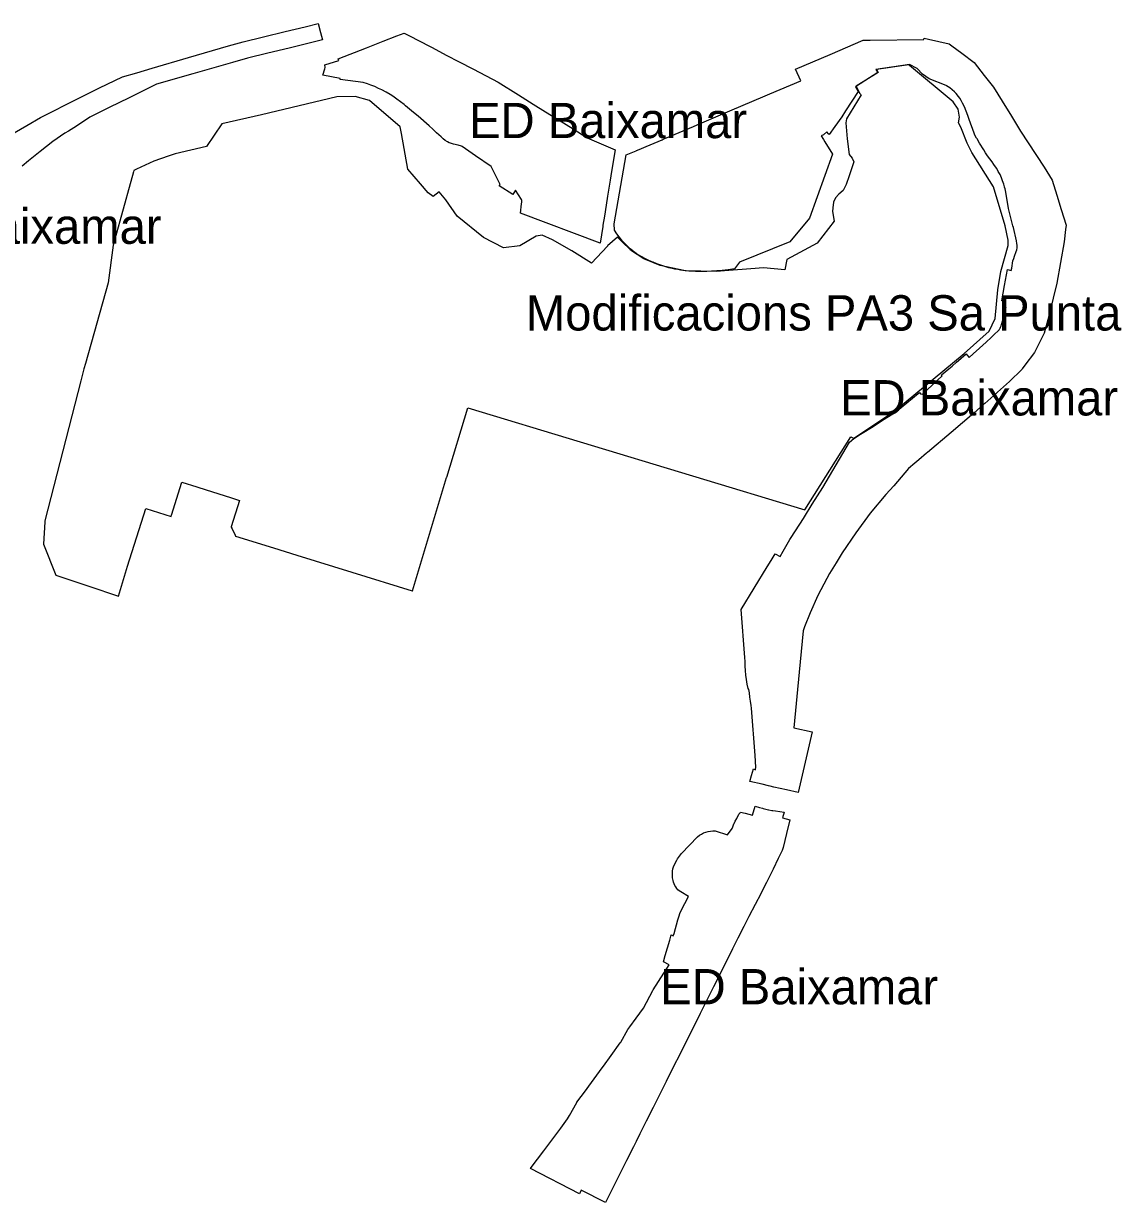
# Model space of a CAD drawing. Extents: x 599912 to 613490, y 4411003 to 4422920.
# Drawn here: x 608791.7 to 609165, y 4416011.2 to 4416412.1 of the extents above; entities that cross this region are included whole.
import ezdxf

# ---------------------------------------------------------------- set-up
doc = ezdxf.new("R2010")
doc.units = 0
doc.layers.add('Estudi de Detall', color=7, linetype='Continuous')
doc.layers.add('Sector amb disposicions transitòries', color=7, linetype='Continuous')

msp = doc.modelspace()

# ---------------------------------------------------------------- linework, layer by layer
at = {"layer": 'Estudi de Detall'}
msp.add_lwpolyline([(608788.56, 4416374.98), (608792.9, 4416377.42), (608797.5, 4416380.16), (608801.83, 4416382.34), (608806.24, 4416384.56), (608810.96, 4416386.95), (608817.59, 4416390.17), (608825.38, 4416393.95), (608830.19, 4416395.36), (608835.5, 4416396.92), (608847.81, 4416400.54), (608861.39, 4416404.46), (608866.43, 4416405.91), (608873.33, 4416407.58), (608880.64, 4416409.35), (608887.44, 4416410.99), (608891.88, 4416412.07), (608892.69, 4416409), (608893.36, 4416406.51), (608882.02, 4416403.74), (608874.78, 4416401.98), (608867.86, 4416400.29), (608862.79, 4416398.84), (608849.28, 4416395), (608836.96, 4416391.49), (608832.39, 4416389.23), (608827.66, 4416386.88), (608820.83, 4416383.49), (608814.23, 4416380.21), (608809.71, 4416377.21), (608806.96, 4416375.51), (608805.75, 4416374.76), (608801.64, 4416371.98), (608797.33, 4416368.59), (608793.4, 4416365.43), (608791.28, 4416363.64)], dxfattribs=at)
for points in [[(608907.15, 4416392), (608899.33, 4416393.09), (608899.4, 4416393.37), (608893.51, 4416394.48), (608894.17, 4416396.73), (608894.3, 4416397.15), (608894.17, 4416398.05), (608898.96, 4416399.47), (608898.74, 4416400.06), (608908.36, 4416403.83), (608914.04, 4416406.05), (608918.63, 4416407.85), (608921.14, 4416408.83), (608921.17, 4416408.84), (608923.45, 4416407.66), (608925.73, 4416406.46), (608930.37, 4416404.04), (608935.66, 4416401.27), (608939.62, 4416399.2), (608944.68, 4416396.55), (608953.12, 4416392.13), (608960.02, 4416387.82), (608965.04, 4416384.68), (608969.22, 4416382.09), (608973.87, 4416379.18), (608978.56, 4416376.25), (608983.38, 4416373.24), (608992.89, 4416369.14), (608991.68, 4416361.73), (608991.21, 4416358.79), (608990.32, 4416353.35), (608989.83, 4416350.33), (608989.22, 4416346.57), (608988.73, 4416343.51), (608988.66, 4416343.1), (608987.74, 4416337.41), (608960.65, 4416347.56), (608960.65, 4416347.57), (608961.03, 4416350.74), (608961.12, 4416351.31), (608961.14, 4416351.77), (608961.11, 4416351.93), (608960.99, 4416352.26), (608959.03, 4416355.4), (608958.13, 4416353.96), (608953.48, 4416356.87), (608953.81, 4416357.39), (608952.57, 4416359.8), (608950.69, 4416363.43), (608945.35, 4416367.14), (608940.85, 4416370.29), (608940.6, 4416370.37), (608939.49, 4416370.74), (608937.87, 4416371.12), (608936.85, 4416371.4), (608936.41, 4416371.57), (608935.84, 4416371.86), (608935.11, 4416372.33), (608934.43, 4416372.84), (608933.66, 4416373.51), (608932.1, 4416374.97), (608930.89, 4416376.12), (608929.58, 4416377.27), (608925.86, 4416380.54), (608924.34, 4416381.87), (608921.59, 4416384.13), (608921.1, 4416384.51), (608918.67, 4416386.41), (608917.25, 4416387.41), (608916.33, 4416387.99), (608915.01, 4416388.76), (608913.59, 4416389.52), (608912.46, 4416390.05), (608911.18, 4416390.63), (608909.79, 4416391.18), (608908.68, 4416391.57), (608908.36, 4416391.66), (608907.55, 4416391.9)], [(609063.68, 4416372.61), (609064.17, 4416371.83), (609066.77, 4416367.68), (609058.98, 4416345.94), (609052.31, 4416337.88), (609035.16, 4416330.97), (609033.4, 4416328.64), (609032.72, 4416328.53), (609031.26, 4416328.35), (609029.2, 4416328.1), (609025.67, 4416327.84), (609024.02, 4416327.8), (609022.13, 4416327.76), (609021.76, 4416327.77), (609020.13, 4416327.81), (609018.59, 4416327.86), (609017.9, 4416327.92), (609017.06, 4416327.99), (609016.64, 4416328.04), (609015.08, 4416328.25), (609014.15, 4416328.42), (609013.11, 4416328.6), (609012.85, 4416328.67), (609011.17, 4416329.06), (609010.47, 4416329.26), (609009.13, 4416329.65), (609007.36, 4416330.26), (609007.02, 4416330.4), (609005.76, 4416330.9), (609005.51, 4416331), (609003.58, 4416331.89), (609002.31, 4416332.55), (609001.92, 4416332.76), (609000.38, 4416333.66), (609000.2, 4416333.77), (609000, 4416333.91), (608999.13, 4416334.57), (608998.9, 4416334.76), (608998.02, 4416335.49), (608997.56, 4416335.91), (608996.97, 4416336.46), (608996.48, 4416336.95), (608995.96, 4416337.48), (608995.3, 4416338.22), (608995, 4416338.56), (608994.21, 4416339.55), (608993.39, 4416340.57), (608992.66, 4416341.78), (608992.49, 4416344.01), (608996.63, 4416367.4), (609000, 4416368.83), (609000.09, 4416368.87), (609001.07, 4416369.28), (609003.44, 4416370.29), (609008.83, 4416372.58), (609009.18, 4416372.73), (609009.77, 4416372.98), (609019.52, 4416377.12), (609021.99, 4416378.17), (609022.35, 4416378.32), (609032.65, 4416382.69), (609043.08, 4416387.12), (609045.48, 4416388.14), (609055.95, 4416392.59), (609054.23, 4416396.62), (609065.97, 4416401.6), (609077.24, 4416406.39), (609077.74, 4416406.4), (609079.58, 4416406.42), (609097.78, 4416406.64), (609097.93, 4416407.09), (609099.37, 4416406.76), (609106.47, 4416405.15), (609107.32, 4416404.51), (609110.68, 4416402), (609114.97, 4416398.8), (609118.31, 4416394.42), (609121.52, 4416390.48), (609124.43, 4416385.72), (609127.6, 4416380.56), (609130.72, 4416375.47), (609133.29, 4416371.54), (609138.67, 4416363.28), (609141.47, 4416358.86), (609143.05, 4416353.71), (609144.55, 4416348.84), (609146.18, 4416343.54), (609146.01, 4416342.04), (609145.55, 4416337.9), (609143.03, 4416323.86), (609141.78, 4416318.73), (609140, 4416311.37), (609138.74, 4416306.77), (609135.44, 4416300.28), (609132.14, 4416295.89), (609131.27, 4416294.73), (609131.09, 4416294.49), (609126.93, 4416290.35), (609122.81, 4416286.73), (609122.63, 4416286.57), (609118.52, 4416282.94), (609118.19, 4416282.66), (609114.76, 4416279.64), (609107.11, 4416273.06), (609099.03, 4416266.23), (609098.76, 4416266), (609096.1, 4416263.75), (609094.74, 4416262.6), (609092.64, 4416260.83), (609087.56, 4416254.87), (609084.89, 4416251.9), (609079.62, 4416245.56), (609074.66, 4416238.97), (609070.05, 4416232.14), (609067.98, 4416228.73), (609065.78, 4416225.09), (609064.81, 4416223.35), (609061.83, 4416217.58), (609059.15, 4416211.67), (609057.29, 4416206.96), (609056.77, 4416205.64), (609055.4, 4416191.52), (609053.58, 4416172.65), (609059.82, 4416171.22), (609055.1, 4416150.58), (609051.09, 4416151.51), (609049, 4416151.99), (609046.87, 4416152.49), (609045.59, 4416152.79), (609044.96, 4416152.94), (609042.9, 4416153.41), (609038.67, 4416154.4), (609039.25, 4416156.4), (609039.91, 4416158.66), (609040.58, 4416158.37), (609040.74, 4416159.23), (609040.44, 4416163.17), (609039.21, 4416179.31), (609039.15, 4416180.22), (609038.89, 4416181.63), (609038.78, 4416182.4), (609038.7, 4416183.05), (609038.58, 4416184.54), (609038.26, 4416185.6), (609038.14, 4416186.01), (609037.78, 4416187.5), (609037.49, 4416189.02), (609037.28, 4416190.54), (609037.14, 4416192.07), (609037.08, 4416193.61), (609037.1, 4416195.14), (609036.99, 4416196.54), (609035.74, 4416212.87), (609044.57, 4416227.33), (609045.93, 4416229.52), (609047.29, 4416231.72), (609048.95, 4416230.86), (609050.01, 4416232.72), (609052.22, 4416236.6), (609052.7, 4416237.35), (609056.86, 4416243.81), (609057.21, 4416244.35), (609059.87, 4416248.65), (609063.45, 4416254.37), (609072.51, 4416269.71), (609074.01, 4416270.98), (609076.3, 4416272.42), (609080.54, 4416275.09), (609084.38, 4416277.52), (609088.15, 4416279.89), (609095.88, 4416286.31), (609096.32, 4416286.67), (609096.73, 4416286.18), (609097.33, 4416286.09), (609104.01, 4416292.31), (609103.78, 4416292.59), (609106.34, 4416294.73), (609107.41, 4416295.62), (609108.94, 4416296.89), (609109.63, 4416297.5), (609112.19, 4416299.76), (609112.45, 4416299.44), (609113.21, 4416298.49), (609114.58, 4416299.75), (609116.72, 4416301.71), (609118.97, 4416303.78), (609120.72, 4416305.38), (609121.96, 4416306.53), (609122.96, 4416307.44), (609123.41, 4416307.94), (609123.69, 4416308.36), (609123.77, 4416308.52), (609123.92, 4416308.82), (609124.11, 4416309.3), (609124.23, 4416309.72), (609124.55, 4416310.9), (609125.12, 4416312.96), (609125.86, 4416315.63), (609124.81, 4416315.95), (609125.21, 4416317.52), (609124.33, 4416317.78), (609124.79, 4416320.39), (609125.27, 4416323.07), (609126.24, 4416328.49), (609127.55, 4416328.13), (609127.69, 4416328.94), (609128.12, 4416331.4), (609128.37, 4416332.25), (609128.59, 4416333.01), (609129.22, 4416334.59), (609129.38, 4416335.09), (609129.51, 4416335.77), (609129.53, 4416336.65), (609129.48, 4416337.36), (609129.36, 4416338.08), (609129.34, 4416338.17), (609128.25, 4416342.7), (609128.09, 4416343.34), (609127.52, 4416345.62), (609126.63, 4416349.2), (609126.6, 4416349.32), (609126.36, 4416350.55), (609125.64, 4416354.8), (609125.42, 4416355.86), (609125.27, 4416356.44), (609125.24, 4416356.55), (609124.98, 4416357.48), (609124.61, 4416358.57), (609124.19, 4416359.66), (609123.71, 4416360.72), (609123.14, 4416361.83), (609122.6, 4416362.76), (609122.21, 4416363.37), (609121.63, 4416364.18), (609121.01, 4416365.06), (609119.48, 4416367.14), (609118.82, 4416368.11), (609118.17, 4416369.11), (609116.72, 4416371.43), (609115.89, 4416372.86), (609115.74, 4416373.11), (609115.19, 4416374.17), (609114.9, 4416374.78), (609113.23, 4416379.51), (609112.79, 4416380.82), (609112.21, 4416382.32), (609111.59, 4416383.74), (609111, 4416385.05), (609110.51, 4416385.97), (609110.06, 4416386.71), (609109.64, 4416387.3), (609108.84, 4416388.26), (609108.23, 4416388.87), (609107.46, 4416389.55), (609106.66, 4416390.18), (609105.57, 4416390.93), (609105.44, 4416391.01), (609099.6, 4416393.28), (609099.59, 4416393.28), (609097.35, 4416394.84), (609095.54, 4416396.76), (609095.53, 4416396.77), (609092.9, 4416398.18), (609081.45, 4416396.48), (609082.17, 4416395.4), (609077.76, 4416392.59), (609074.61, 4416390.58), (609075.49, 4416388.96), (609071.2, 4416382.36), (609069.89, 4416380.34), (609067.6, 4416377.13), (609065.6, 4416374.34), (609065.39, 4416374.57), (609064.82, 4416375.21), (609063.73, 4416374.26), (609062.87, 4416373.9)], [(608989.61, 4416011.24), (608981.29, 4416015.39), (608980.7, 4416014.21), (608964.07, 4416022.74), (608964.08, 4416022.74), (608964.35, 4416023.14), (608968.57, 4416028.76), (608974.05, 4416035.98), (608974.42, 4416036.5), (608976.65, 4416039.62), (608977.33, 4416040.82), (608979.83, 4416045.22), (608979.89, 4416045.31), (608982.79, 4416049.23), (608983.97, 4416050.81), (608985.77, 4416053.29), (608988.46, 4416056.97), (608988.91, 4416057.59), (608991.56, 4416061.24), (608994.61, 4416065.45), (608994.75, 4416065.7), (608997.16, 4416070.01), (608997.86, 4416070.97), (609000, 4416073.88), (609002.47, 4416077.24), (609005.73, 4416083.33), (609005.84, 4416083.51), (609011.18, 4416092.08), (609009.29, 4416093.02), (609009.92, 4416095.17), (609011.45, 4416100.45), (609011.89, 4416102.2), (609012.55, 4416101.91), (609012.9, 4416102.71), (609014.13, 4416107.33), (609014.59, 4416108.64), (609014.9, 4416109.49), (609015.36, 4416110.48), (609017.78, 4416115.26), (609015.15, 4416116.81), (609014.67, 4416117.17), (609014.22, 4416117.57), (609013.82, 4416118.02), (609013.47, 4416118.5), (609013.17, 4416119.02), (609012.91, 4416119.57), (609012.72, 4416120.13), (609012.58, 4416120.72), (609012.41, 4416121.64), (609012.32, 4416122.4), (609012.31, 4416123.16), (609012.38, 4416123.92), (609012.52, 4416124.67), (609012.73, 4416125.4), (609013.02, 4416126.1), (609013.79, 4416127.58), (609014.08, 4416128.06), (609014.39, 4416128.53), (609014.73, 4416128.99), (609015.09, 4416129.43), (609015.47, 4416129.85), (609020.91, 4416135.59), (609021.52, 4416136.07), (609022.19, 4416136.51), (609022.91, 4416136.88), (609023.67, 4416137.17), (609024.45, 4416137.39), (609025.24, 4416137.53), (609026.05, 4416137.59), (609026.86, 4416137.56), (609031.04, 4416136.24), (609032.6, 4416138.43), (609032.82, 4416138.99), (609033.24, 4416139.93), (609033.32, 4416140.09), (609033.7, 4416140.84), (609034.21, 4416141.74), (609034.87, 4416143.28), (609035.42, 4416143.7), (609035.5, 4416143.97), (609037.03, 4416143.65), (609039.56, 4416142.88), (609040.49, 4416145.95), (609041.98, 4416145.5), (609042.97, 4416145.27), (609043.21, 4416145.21), (609045.04, 4416144.78), (609045.1, 4416144.77), (609046.18, 4416144.52), (609046.43, 4416144.48), (609047.38, 4416144.34), (609050.34, 4416143.91), (609049.81, 4416142.03), (609052.27, 4416141.34), (609051.13, 4416136.73), (609049.94, 4416131.91), (609049.7, 4416130.91), (609048.28, 4416128.21), (609046.62, 4416124.55), (609044.89, 4416121.14), (609044.34, 4416120.06), (609043.78, 4416118.96), (609042.36, 4416116.17), (609040.5, 4416112.52), (609038.33, 4416108.46), (609036.64, 4416105.11), (609034.6, 4416101.1), (609032.76, 4416097.42), (609030.91, 4416093.7), (609026.31, 4416084.52), (609021.74, 4416075.49), (609015.15, 4416062.26), (609012.4, 4416056.73), (609010.23, 4416052.37), (609008.05, 4416048.05), (609005.76, 4416043.49), (609003.43, 4416038.86), (609001.29, 4416034.59), (609000, 4416032.01), (608999.08, 4416030.18), (608996.7, 4416025.44), (608995.12, 4416022.28)]]:
    msp.add_lwpolyline(points, close=True, dxfattribs=at)
at = {"layer": 'Sector amb disposicions transitòries'}
msp.add_lwpolyline([(608829.2, 4416362.12), (608829.09, 4416361.7), (608824.49, 4416344.88), (608822.25, 4416336.72), (608820.54, 4416323.94), (608812.8, 4416296.53), (608812.28, 4416294.72), (608811.22, 4416290.59), (608799.02, 4416242.99), (608799, 4416242.68), (608798.5, 4416235.08), (608802.7, 4416224.56), (608813.87, 4416220.79), (608823.96, 4416217.38), (608827.09, 4416227.61), (608833.33, 4416247.14), (608841.92, 4416244.46), (608842.08, 4416244.97), (608845.57, 4416256.1), (608850.68, 4416254.5), (608853.81, 4416253.51), (608862.13, 4416250.9), (608865.17, 4416249.95), (608862.35, 4416240.97), (608862.32, 4416240.87), (608862.62, 4416240.26), (608863.65, 4416238.12), (608863.78, 4416237.83), (608876.67, 4416233.84), (608884.68, 4416231.36), (608903.33, 4416225.58), (608923.9, 4416219.14), (608923.92, 4416219.21), (608935.57, 4416257.68), (608935.6, 4416257.79), (608942.76, 4416281.45), (609057.41, 4416246.79), (609073.02, 4416271.58), (609073.87, 4416271.08), (609073.96, 4416271.13), (609087.87, 4416280.27), (609111.48, 4416299.87), (609120.03, 4416307.48), (609122.05, 4416311.77), (609122.97, 4416321.54), (609123.97, 4416327.77), (609126.48, 4416336.59), (609126.51, 4416338.41), (609125.41, 4416343.29), (609121.53, 4416356.57), (609114.16, 4416368.22), (609112.49, 4416371.38), (609110.41, 4416376.8), (609109.57, 4416378.35), (609109.99, 4416380.27), (609109.45, 4416382.94), (609107.84, 4416385.48), (609092.93, 4416397.82), (609092.66, 4416398.05), (609081.71, 4416396.49), (609082.29, 4416395.39), (609074.76, 4416390.74), (609075.51, 4416389.34), (609076.07, 4416388.29), (609076.46, 4416387.9), (609071.54, 4416379.65), (609071.28, 4416378.27), (609071.72, 4416372.88), (609072.38, 4416367.59), (609073.41, 4416366.29), (609073.97, 4416365.01), (609072.43, 4416360.3), (609071.35, 4416357.4), (609070.39, 4416355.31), (609068.93, 4416354.08), (609067.76, 4416352.85), (609067.13, 4416351.3), (609066.88, 4416349.47), (609066.71, 4416348.21), (609067.28, 4416344.85), (609061.51, 4416337.41), (609051.27, 4416331.8), (609050.57, 4416328.29), (609043.29, 4416329.06), (609038.99, 4416328.7), (609031.49, 4416328.09), (609027.17, 4416327.74), (609016.76, 4416327.98), (609008.2, 4416329.76), (609002.64, 4416332.06), (608998.46, 4416334.84), (608998.12, 4416335.07), (608997.97, 4416335.2), (608995.38, 4416337.73), (608994, 4416339.08), (608993.62, 4416339.45), (608990.31, 4416336.46), (608990.23, 4416336.38), (608984.86, 4416330.56), (608978.16, 4416334.84), (608971.52, 4416338.53), (608968.03, 4416340.12), (608965.96, 4416339.76), (608960.49, 4416336.45), (608954.88, 4416335.84), (608948.14, 4416339.32), (608939.19, 4416346.54), (608935.34, 4416352.14), (608933.02, 4416354.82), (608930.94, 4416353.23), (608929.24, 4416354.55), (608926.66, 4416357.57), (608922.38, 4416362.55), (608920.19, 4416374.68), (608919.78, 4416376.95), (608909.4, 4416385.89), (608909.32, 4416385.96), (608904.53, 4416387.25), (608898.29, 4416387.11), (608872.63, 4416381.1), (608859.15, 4416377.94), (608853.92, 4416370.32), (608843.32, 4416367.74), (608840.86, 4416367.02), (608836.01, 4416365.33), (608830.11, 4416362.55)], close=True, dxfattribs=at)

# ---------------------------------------------------------------- texts
at = {"layer": 'Estudi de Detall'}
for p in [(608943.2, 4416373.12), (608744.13, 4416337.19), (609069.34, 4416278.83), (609008.17, 4416078.59)]:
    msp.add_text('ED Baixamar', height=12, dxfattribs=at).set_placement(p)
at = {"layer": 'Sector amb disposicions transitòries'}
msp.add_text('Modificacions PA3 Sa Punta', height=12, dxfattribs=at).set_placement((608962.51, 4416307.71))

doc.saveas('drawing.dxf')
